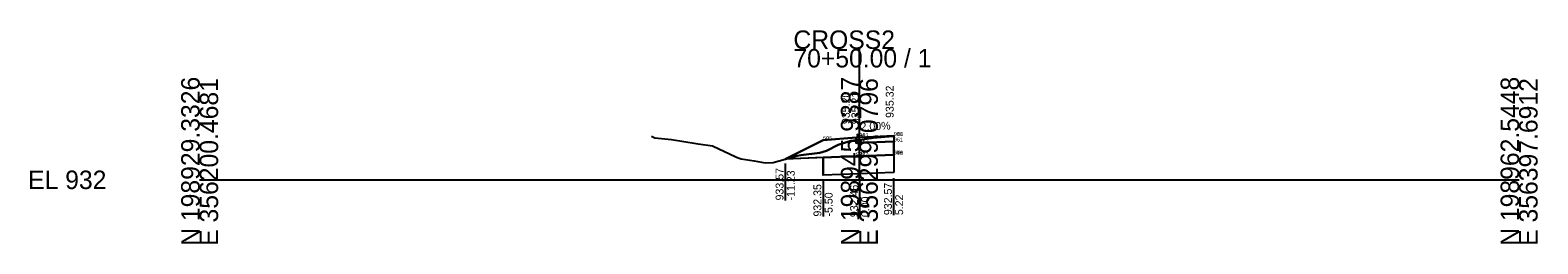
# Model space of a CAD drawing. Extents: x -26 to 203, y -10 to 14021.
# Drawn here: x -25.7 to 202.8, y 11490.3 to 11522.7 of the extents above; entities that cross this region are included whole.
import ezdxf

# ---------------------------------------------------------------- set-up
doc = ezdxf.new("R2010")
doc.units = 0
for name, color, linetype in [('Default', 7, 'Continuous'), ('P_E_XS_Ground', 7, 'Continuous'), ('P_XS', 7, 'Continuous'), ('P_XS_Bold', 7, 'Continuous'), ('P_XS_EAR_CommonGrnd', 7, 'Continuous'), ('P_XS_Lane', 7, 'Continuous'), ('P_XS_Rock', 7, 'Continuous')]:
    doc.layers.add(name, color=color, linetype=linetype)

msp = doc.modelspace()

# ---------------------------------------------------------------- linework, layer by layer
at = {"layer": 'Default'}
for p, q in [((100, 11500), (100, 11519.82)), ((0, 11500), (100, 11500)), ((100, 11500), (200, 11500))]:
    msp.add_line(p, q, dxfattribs=at)
at = {"layer": 'P_E_XS_Ground'}
for p, q in [((105.08, 11506.61), (105.34, 11506.66)), ((68.47, 11506.59), (68.98, 11506.37)), ((68.98, 11506.37), (71.54, 11506.1)), ((71.54, 11506.1), (75.25, 11505.48)), ((75.25, 11505.48), (75.56, 11505.43)), ((75.56, 11505.43), (77.72, 11505.16)), ((77.72, 11505.16), (81.28, 11503.48)), ((94.03, 11504.07), (95, 11504.39)), ((95, 11504.39), (96.78, 11505.3)), ((96.78, 11505.3), (98.41, 11505.78)), ((98.41, 11505.78), (98.72, 11505.88)), ((98.72, 11505.88), (100, 11506.05)), ((100, 11506.05), (101.86, 11506.31)), ((101.86, 11506.31), (102.39, 11506.4)), ((102.39, 11506.4), (102.69, 11506.42)), ((102.69, 11506.42), (105.08, 11506.61)), ((81.28, 11503.48), (81.62, 11503.35)), ((81.62, 11503.35), (82.07, 11503.17)), ((82.07, 11503.17), (84.07, 11502.86)), ((84.07, 11502.86), (85.74, 11502.58)), ((85.74, 11502.58), (86.92, 11502.63)), ((86.92, 11502.63), (90.56, 11503.64)), ((90.56, 11503.64), (91.12, 11503.73)), ((91.12, 11503.73), (94.03, 11504.07))]:
    msp.add_line(p, q, dxfattribs=at)
at = {"layer": 'P_XS'}
for p, q in [((105.22, 11506.64), (105.22, 11505.8)), ((99.5, 11505.57), (99.5, 11506.41)), ((99.5, 11505.57), (100, 11505.59)), ((105.22, 11505.8), (100, 11505.59)), ((105.22, 11503.8), (105.22, 11505.8)), ((99.5, 11503.57), (88.77, 11503.14)), ((94.5, 11503.37), (94.5, 11500.7)), ((99.5, 11503.57), (100, 11503.59)), ((105.22, 11503.8), (100, 11503.59)), ((105.22, 11503.8), (105.22, 11501.13)), ((105.22, 11501.13), (94.5, 11500.7))]:
    msp.add_line(p, q, dxfattribs=at)
at = {"layer": 'P_XS_EAR_CommonGrnd'}
for points in [[(102.39, 11506.4), (102.69, 11506.42), (105.08, 11506.61), (105.22, 11506.64), (100, 11506.43), (99.5, 11506.41), (99.5, 11505.98), (100, 11506.05), (101.86, 11506.31)], [(102.39, 11506.4), (102.69, 11506.42), (105.08, 11506.61), (105.22, 11506.64), (105.22, 11505.8), (100, 11505.59), (99.5, 11505.57), (99.5, 11505.98), (100, 11506.05), (101.86, 11506.31)], [(88.79, 11503.14), (88.77, 11503.14), (94.5, 11506.01), (99.5, 11506.41), (99.5, 11505.98), (98.72, 11505.88), (98.41, 11505.78), (96.78, 11505.3), (95, 11504.39), (94.03, 11504.07), (91.12, 11503.73), (90.56, 11503.64)], [(94.5, 11503.37), (88.79, 11503.14), (90.56, 11503.64), (91.12, 11503.73), (94.03, 11504.07), (95, 11504.39), (96.78, 11505.3), (98.41, 11505.78), (98.72, 11505.88), (99.5, 11505.98), (99.5, 11505.57), (100, 11505.59), (105.22, 11505.8), (105.22, 11503.8), (100, 11503.59), (99.5, 11503.57)], [(105.22, 11501.13), (94.5, 11500.7), (94.5, 11503.37), (99.5, 11503.57), (100, 11503.59), (105.22, 11503.8)]]:
    msp.add_lwpolyline(points, close=True, dxfattribs=at)
at = {"layer": 'P_XS_Lane'}
for p, q in [((100, 11506.43), (105.22, 11506.64)), ((94.5, 11506.01), (88.76, 11503.14)), ((99.5, 11506.41), (94.5, 11506.01)), ((99.5, 11506.41), (100, 11506.43))]:
    msp.add_line(p, q, dxfattribs=at)
at = {"layer": 'P_XS_Rock'}
for p, q in [((88.75, 11502.47), (88.75, 11496.87)), ((94.49, 11500.03), (94.49, 11494.44)), ((100.04, 11499.95), (100.04, 11494.35)), ((105.18, 11500.24), (105.18, 11494.65))]:
    msp.add_line(p, q, dxfattribs=at)

# ---------------------------------------------------------------- texts
at = {"layer": 'Default'}
for s, p in [('CROSS2', (90, 11519.82)), ('70+50.00 / 1', (90, 11517.02)), ('EL 932', (-26, 11498.6))]:
    msp.add_text(s, height=2.8, dxfattribs=at).set_placement(p)
for s, p in [('N 198929.3326', (0, 11490)), ('E 356200.4681', (2.8, 11490)), ('N 198945.9387', (100, 11490)), ('E 356299.0796', (102.8, 11490)), ('N 198962.5448', (200, 11490)), ('E 356397.6912', (202.8, 11490))]:
    msp.add_text(s, height=2.8, rotation=90, dxfattribs=at).set_placement(p)
at = {"layer": 'P_XS_Bold'}
for s, p in [('951', (99.5, 11506.41)), ('9', (99.5, 11506.41)), ('900', (99.5, 11506.41)), ('952', (100, 11506.43)), ('952', (100, 11506.43)), ('951', (105.22, 11506.64)), ('9', (105.22, 11506.64)), ('900', (105.22, 11506.64)), ('910', (105.22, 11506.64)), ('505', (94.5, 11506.01)), ('961', (99.5, 11505.57)), ('962', (100, 11505.59)), ('962', (100, 11505.59)), ('961', (105.22, 11505.8)), ('971', (105.22, 11503.8)), ('998', (105.22, 11503.8)), ('540', (105.22, 11503.8)), ('971', (99.5, 11503.57)), ('998', (99.5, 11503.57)), ('972', (100, 11503.59)), ('972', (100, 11503.59))]:
    msp.add_text(s, height=0.6, dxfattribs=at).set_placement(p)
at = {"layer": 'P_XS_Rock'}
for s, rotation, p in [('935.32', 90, (105.2, 11509.37)), ('935.20', 90, (98.54, 11508.44)), ('935.21', 90, (100, 11508.43)), ('935.21', 90, (100, 11508.43)), ('935.21', 90, (100, 11508.43)), ('935.21', 90, (100, 11508.43)), ('2.00%', 2.2906, (100.2, 11507.44)), ('933.57', 90, (88.5, 11496.88)), ('-11.23', 90, (90.2, 11496.88)), ('932.35', 90, (94.24, 11494.44)), ('-5.50', 90, (95.94, 11494.44)), ('932.46', 90, (99.79, 11494.35)), ('932.57', 90, (104.93, 11494.65)), ('5.22', 90, (106.63, 11494.65)), ('0.00', 90, (101.49, 11494.35))]:
    msp.add_text(s, height=1.2, rotation=rotation, dxfattribs=at).set_placement(p)

doc.saveas('drawing.dxf')
